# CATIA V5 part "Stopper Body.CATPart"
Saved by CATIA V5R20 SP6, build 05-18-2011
Part number: Stopper Body
Bounding box of the stored display mesh (mm): x 0 to 7, y -3.5 to 3.5, z -10 to 10
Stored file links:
  E:\#01 CATIA Lecture Materials\#06 DMU\#03 DMU Page01 KIN EX03\Stopper Body.CATPart
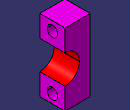
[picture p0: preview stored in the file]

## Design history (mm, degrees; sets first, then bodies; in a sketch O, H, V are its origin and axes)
Set1 "Reference Data"
  Point1 "Center Point": (0, 0, 0)
  Plane1 "Plane.1(X Dir = 7mm)": type Offset, RefPlane yz-plane, Offset 7
Body1 (main body)
  Body2
    Sketch1 on yz-plane, origin (0, 0, 0), H (0, 1, 0), V (0, 0, 1)
      line L1 (3.5, 10) -> (3.5, -10)
      line L2 (3.5, -10) -> (-3.5, -10)
      line L3 (-3.5, -10) -> (-3.5, 10)
      line L4 (-3.5, 10) -> (3.5, 10)
      circle A1 centre (0, 7.5) radius 1.5
      point P5 (0, 7.5)
      point P6 (0, -7.5)
      circle A2 centre (0, -7.5) radius 1.5
      distance L3 L1 = 7
      distance L4 L2 = 20
      radius A1 = 1.5
      distance P5 P6 = 15
      vertical: L1 V, L3 V
      horizontal: L2 H, L4 H
      equidistance: L1 L3 O, L2 L4 O
      coincidence: P5 V
      symmetry: A1 A2 H
    Pad1: profile Sketch1, direction (1, 0, 0), up to Plane1
  Assemble1: tool Body2
  Body3 "Hole Body"
    Sketch2 on zx-plane, origin (0, 0, 0), H (-1, 0, 0), V (0, 0, 1)
      circle A1 centre (-7, 0) radius 4
      point P1 (-7, 0)
      reference intersected line E1 through (-7, 0) direction (0, -1) from Plane1
      radius A1 = 4
      coincidence: P1 H, P1 E1
    Pad2: profile Sketch2, direction (0, 1, 0), length 7, mirrored extent
  Remove1: tool Body3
